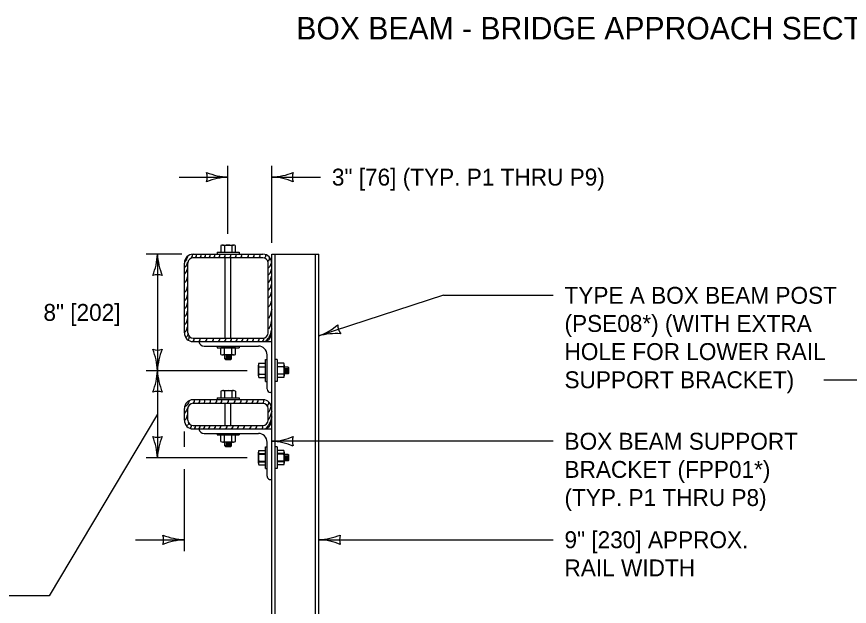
# Model space of a CAD drawing. Extents: x 49991.4 to 50021, y 49987.6 to 50011.4.
# Drawn here: x 50004.991 to 50007.949, y 49989.313 to 49991.409 of the extents above; entities that cross this region are included whole.
import ezdxf

# ---------------------------------------------------------------- set-up
doc = ezdxf.new("R2010")
doc.units = 0
for name, color, linetype in [('Level 1', 7, 'Continuous'), ('Level 2', 7, 'Continuous'), ('Level 3', 7, 'Continuous'), ('Level 4', 7, 'Continuous')]:
    doc.layers.add(name, color=color, linetype=linetype)

msp = doc.modelspace()

# ---------------------------------------------------------------- linework, layer by layer
at = {"layer": 'Level 1'}
for p, q in [((50005.7166, 49990.595), (50005.7166, 49990.5713)), ((50005.723, 49990.5966), (50005.7613, 49990.5966)), ((50005.7293, 49990.595), (50005.7293, 49990.5714)), ((50005.7551, 49990.595), (50005.7551, 49990.5714)), ((50005.7678, 49990.595), (50005.7678, 49990.5713)), ((50005.618, 49990.5649), (50005.866, 49990.5649)), ((50005.7035, 49990.5713), (50005.7811, 49990.5713)), ((50005.7035, 49990.5713), (50005.7035, 49990.5649)), ((50005.7166, 49990.5713), (50005.7678, 49990.5713)), ((50005.7811, 49990.5713), (50005.7811, 49990.5649)), ((50005.8976, 49988.7839), (50005.8976, 49990.5649)), ((50005.8976, 49990.5649), (50006.0648, 49990.5649)), ((50005.9099, 49988.7839), (50005.9099, 49990.5649)), ((50006.0527, 49988.7839), (50006.0527, 49990.5649)), ((50006.0648, 49988.7839), (50006.0648, 49990.5649)), ((50005.5872, 49990.285), (50005.5872, 49990.5333)), ((50005.5993, 49990.285), (50005.5993, 49990.5333)), ((50005.6184, 49990.5523), (50005.866, 49990.5523)), ((50005.7325, 49990.2665), (50005.7325, 49990.5523)), ((50005.7361, 49990.5523), (50005.7484, 49990.5523)), ((50005.7519, 49990.2665), (50005.7519, 49990.5523)), ((50005.8851, 49990.285), (50005.8851, 49990.5333)), ((50005.8976, 49990.285), (50005.8976, 49990.5333)), ((50005.6184, 49990.2665), (50005.866, 49990.2665)), ((50005.6184, 49990.2543), (50005.8976, 49990.2543)), ((50005.6576, 49990.2379), (50005.8503, 49990.2379)), ((50005.7038, 49990.2381), (50005.7038, 49990.2323)), ((50005.7038, 49990.2323), (50005.7814, 49990.2323)), ((50005.7681, 49990.2323), (50005.7169, 49990.2323)), ((50005.7169, 49990.2086), (50005.7169, 49990.2323)), ((50005.7296, 49990.2086), (50005.7296, 49990.2322)), ((50005.7554, 49990.2086), (50005.7554, 49990.2322)), ((50005.7681, 49990.2086), (50005.7681, 49990.2323)), ((50005.7814, 49990.2381), (50005.7814, 49990.2323)), ((50005.7617, 49990.207), (50005.7234, 49990.207)), ((50005.7308, 49990.1931), (50005.7308, 49990.207)), ((50005.7342, 49990.2037), (50005.7507, 49990.2037)), ((50005.7342, 49990.2014), (50005.7507, 49990.2014)), ((50005.7542, 49990.1931), (50005.7542, 49990.207)), ((50005.8813, 49990.0859), (50005.8813, 49990.2072)), ((50005.7542, 49990.1931), (50005.7308, 49990.1931)), ((50005.7308, 49990.1931), (50005.7331, 49990.1908)), ((50005.7331, 49990.1908), (50005.7519, 49990.1908)), ((50005.7342, 49990.199), (50005.7507, 49990.199)), ((50005.7342, 49990.1967), (50005.7507, 49990.1967)), ((50005.7542, 49990.1931), (50005.7519, 49990.1908)), ((50005.8517, 49990.1772), (50005.8754, 49990.1772)), ((50005.8754, 49990.1128), (50005.8754, 49990.1904)), ((50005.8754, 49990.1904), (50005.8817, 49990.1904)), ((50005.8754, 49990.1259), (50005.8754, 49990.1772)), ((50005.9165, 49990.1904), (50005.9102, 49990.1904)), ((50005.9165, 49990.1904), (50005.9165, 49990.1128)), ((50005.9165, 49990.1772), (50005.9165, 49990.126)), ((50005.9402, 49990.1772), (50005.9165, 49990.1772)), ((50005.8501, 49990.1324), (50005.8501, 49990.1707)), ((50005.8516, 49990.1645), (50005.8753, 49990.1645)), ((50005.9403, 49990.1645), (50005.9166, 49990.1645)), ((50005.9418, 49990.1708), (50005.9418, 49990.1325)), ((50005.9557, 49990.1633), (50005.9418, 49990.1633)), ((50005.945, 49990.1433), (50005.945, 49990.1598)), ((50005.9474, 49990.1433), (50005.9474, 49990.1598)), ((50005.9498, 49990.1433), (50005.9498, 49990.1598)), ((50005.9521, 49990.1433), (50005.9521, 49990.1598)), ((50005.9557, 49990.1633), (50005.9557, 49990.1399)), ((50005.9557, 49990.1633), (50005.958, 49990.161)), ((50005.9557, 49990.1399), (50005.958, 49990.1422)), ((50005.958, 49990.1422), (50005.958, 49990.161)), ((50005.8516, 49990.1386), (50005.8753, 49990.1386)), ((50005.8517, 49990.1259), (50005.8754, 49990.1259)), ((50005.8754, 49990.1128), (50005.8817, 49990.1128)), ((50005.9165, 49990.1128), (50005.9102, 49990.1128)), ((50005.9402, 49990.126), (50005.9165, 49990.126)), ((50005.9403, 49990.1387), (50005.9166, 49990.1387)), ((50005.9557, 49990.1399), (50005.9418, 49990.1399)), ((50005.7038, 49990.0548), (50005.7814, 49990.0548)), ((50005.7038, 49990.0548), (50005.7038, 49990.0485)), ((50005.7169, 49990.0785), (50005.7169, 49990.0548)), ((50005.7169, 49990.0548), (50005.7681, 49990.0548)), ((50005.7233, 49990.0801), (50005.7616, 49990.0801)), ((50005.7296, 49990.0785), (50005.7296, 49990.0549)), ((50005.7554, 49990.0785), (50005.7554, 49990.0549)), ((50005.7681, 49990.0785), (50005.7681, 49990.0548)), ((50005.7814, 49990.0548), (50005.7814, 49990.0485)), ((50005.8976, 49990.0733), (50005.8935, 49990.0733)), ((50005.6184, 49990.0479), (50005.866, 49990.0479)), ((50005.6184, 49990.0352), (50005.866, 49990.0352)), ((50005.7325, 49989.9565), (50005.7325, 49990.0352)), ((50005.7361, 49990.0352), (50005.7484, 49990.0352)), ((50005.7519, 49989.9565), (50005.7519, 49990.0352)), ((50005.5872, 49989.975), (50005.5872, 49990.0167)), ((50005.5993, 49989.975), (50005.5993, 49990.0167)), ((50005.8851, 49989.975), (50005.8851, 49990.0167)), ((50005.6184, 49989.9565), (50005.866, 49989.9565)), ((50005.6184, 49989.9442), (50005.8976, 49989.9442)), ((50005.6576, 49989.9279), (50005.8503, 49989.9279)), ((50005.7038, 49989.9281), (50005.7038, 49989.9222)), ((50005.7038, 49989.9222), (50005.7814, 49989.9222)), ((50005.7681, 49989.9222), (50005.7169, 49989.9222)), ((50005.7169, 49989.8985), (50005.7169, 49989.9222)), ((50005.7296, 49989.8985), (50005.7296, 49989.9221)), ((50005.7554, 49989.8985), (50005.7554, 49989.9221)), ((50005.7681, 49989.8985), (50005.7681, 49989.9222)), ((50005.7814, 49989.9281), (50005.7814, 49989.9222)), ((50005.7617, 49989.8969), (50005.7234, 49989.8969)), ((50005.7308, 49989.8831), (50005.7308, 49989.897)), ((50005.7542, 49989.8831), (50005.7308, 49989.8831)), ((50005.7308, 49989.8831), (50005.7331, 49989.8808)), ((50005.7331, 49989.8808), (50005.7519, 49989.8808)), ((50005.7342, 49989.8937), (50005.7507, 49989.8937)), ((50005.7342, 49989.8914), (50005.7507, 49989.8914)), ((50005.7342, 49989.889), (50005.7507, 49989.889)), ((50005.7342, 49989.8867), (50005.7507, 49989.8867)), ((50005.7542, 49989.8831), (50005.7519, 49989.8808)), ((50005.7542, 49989.8831), (50005.7542, 49989.897)), ((50005.8754, 49989.8029), (50005.8754, 49989.8805)), ((50005.8754, 49989.8805), (50005.8817, 49989.8805)), ((50005.8813, 49989.7759), (50005.8813, 49989.8973)), ((50005.9165, 49989.8805), (50005.9102, 49989.8805)), ((50005.9165, 49989.8805), (50005.9165, 49989.8029)), ((50005.8501, 49989.8225), (50005.8501, 49989.8608)), ((50005.8516, 49989.8546), (50005.8753, 49989.8546)), ((50005.8517, 49989.8673), (50005.8754, 49989.8673)), ((50005.8754, 49989.816), (50005.8754, 49989.8673)), ((50005.9165, 49989.8673), (50005.9165, 49989.8161)), ((50005.9402, 49989.8673), (50005.9165, 49989.8673)), ((50005.9403, 49989.8546), (50005.9166, 49989.8546)), ((50005.9418, 49989.8609), (50005.9418, 49989.8226)), ((50005.9557, 49989.8534), (50005.9418, 49989.8534)), ((50005.945, 49989.8334), (50005.945, 49989.8499)), ((50005.9474, 49989.8334), (50005.9474, 49989.8499)), ((50005.9498, 49989.8334), (50005.9498, 49989.8499)), ((50005.9521, 49989.8334), (50005.9521, 49989.8499)), ((50005.9557, 49989.8534), (50005.9557, 49989.83)), ((50005.9557, 49989.8534), (50005.958, 49989.8511)), ((50005.958, 49989.8323), (50005.958, 49989.8511)), ((50005.8516, 49989.8287), (50005.8753, 49989.8287)), ((50005.9403, 49989.8288), (50005.9166, 49989.8288)), ((50005.9557, 49989.83), (50005.9418, 49989.83)), ((50005.9557, 49989.83), (50005.958, 49989.8323)), ((50005.8517, 49989.816), (50005.8754, 49989.816)), ((50005.8754, 49989.8029), (50005.8817, 49989.8029)), ((50005.9165, 49989.8029), (50005.9102, 49989.8029)), ((50005.9402, 49989.8161), (50005.9165, 49989.8161))]:
    msp.add_line(p, q, dxfattribs=at)
for points in [[(50005.5876, 49990.5359), (50005.5931, 49990.5421), (50005.5962, 49990.5479), (50005.5988, 49990.5568)], [(50005.6088, 49990.5496), (50005.6136, 49990.5536), (50005.6156, 49990.5574), (50005.6156, 49990.5639)], [(50005.6268, 49990.5523), (50005.6305, 49990.5579), (50005.6305, 49990.5649)], [(50005.6428, 49990.5523), (50005.647, 49990.5579), (50005.6458, 49990.5649)], [(50005.6585, 49990.5523), (50005.6622, 49990.5574), (50005.6616, 49990.5639)], [(50005.6749, 49990.5523), (50005.6785, 49990.5579), (50005.6785, 49990.5639)], [(50005.6916, 49990.5523), (50005.6953, 49990.5579), (50005.6953, 49990.5639)], [(50005.7092, 49990.5523), (50005.7134, 49990.5579), (50005.7129, 49990.5639)], [(50005.7288, 49990.5523), (50005.7318, 49990.5574), (50005.7318, 49990.5639)], [(50005.7478, 49990.5523), (50005.7515, 49990.5579), (50005.7515, 49990.5639)], [(50005.7672, 49990.5523), (50005.771, 49990.5579), (50005.771, 49990.5639)], [(50005.7874, 49990.5523), (50005.7911, 49990.5579), (50005.7904, 49990.5639)], [(50005.8112, 49990.5523), (50005.8143, 49990.5579), (50005.8143, 49990.5649)], [(50005.8312, 49990.5523), (50005.8353, 49990.5579), (50005.8348, 49990.5639)], [(50005.8516, 49990.5523), (50005.856, 49990.5579), (50005.855, 49990.5639)], [(50005.8718, 49990.5512), (50005.8762, 49990.5568), (50005.8762, 49990.5632)], [(50005.5867, 49990.5171), (50005.5931, 49990.5227), (50005.5966, 49990.5299), (50005.5993, 49990.5373)], [(50005.8857, 49990.5401), (50005.8888, 49990.5459), (50005.8888, 49990.5523)], [(50005.8861, 49990.5159), (50005.8919, 49990.5221), (50005.8945, 49990.5279), (50005.8972, 49990.5373)], [(50005.5876, 49990.4941), (50005.5931, 49990.5008), (50005.5962, 49990.5067), (50005.5988, 49990.5159)], [(50005.8861, 49990.491), (50005.8915, 49990.4968), (50005.894, 49990.503), (50005.8968, 49990.5114)], [(50005.5872, 49990.4628), (50005.5931, 49990.4693), (50005.5958, 49990.4751), (50005.5982, 49990.4842)], [(50005.8861, 49990.4645), (50005.8915, 49990.4709), (50005.894, 49990.4777), (50005.8968, 49990.4862)], [(50005.5872, 49990.4287), (50005.5931, 49990.4348), (50005.5958, 49990.4407), (50005.5982, 49990.4498)], [(50005.8861, 49990.4371), (50005.8915, 49990.4434), (50005.894, 49990.4491), (50005.8968, 49990.4583)], [(50005.5876, 49990.399), (50005.5931, 49990.4052), (50005.5962, 49990.4112), (50005.5982, 49990.4202)], [(50005.8861, 49990.4095), (50005.8915, 49990.4153), (50005.894, 49990.4219), (50005.8968, 49990.4301)], [(50005.5876, 49990.3705), (50005.5931, 49990.3763), (50005.5962, 49990.3826), (50005.5982, 49990.3915)], [(50005.8861, 49990.3773), (50005.8915, 49990.3831), (50005.894, 49990.3889), (50005.8968, 49990.3983)], [(50005.5876, 49990.3415), (50005.5931, 49990.3479), (50005.5962, 49990.3537), (50005.5982, 49990.3626)], [(50005.8972, 49990.3683), (50005.8945, 49990.3571), (50005.8915, 49990.3466), (50005.8857, 49990.3361)], [(50005.5876, 49990.3135), (50005.5931, 49990.3197), (50005.5962, 49990.3255), (50005.5982, 49990.3346)], [(50005.8968, 49990.3308), (50005.8945, 49990.3197), (50005.8915, 49990.3091), (50005.8857, 49990.2986)], [(50005.5876, 49990.2866), (50005.5931, 49990.2927), (50005.5962, 49990.2986), (50005.5982, 49990.3071)], [(50005.8972, 49990.2996), (50005.8945, 49990.289), (50005.8915, 49990.278), (50005.8857, 49990.2675), (50005.8766, 49990.2569)], [(50005.6003, 49990.2839), (50005.5982, 49990.276), (50005.5962, 49990.2712), (50005.5915, 49990.2696)], [(50005.6014, 49990.2607), (50005.6046, 49990.2665), (50005.6046, 49990.2723)], [(50005.6184, 49990.2543), (50005.622, 49990.2607), (50005.6214, 49990.2665)], [(50005.6395, 49990.2543), (50005.6432, 49990.2601), (50005.6432, 49990.2659)], [(50005.6622, 49990.2543), (50005.6664, 49990.2601), (50005.6664, 49990.2659)], [(50005.6875, 49990.2543), (50005.6907, 49990.2607), (50005.6907, 49990.2665)], [(50005.7087, 49990.2543), (50005.7129, 49990.2607), (50005.7124, 49990.2665)], [(50005.7297, 49990.2543), (50005.7341, 49990.2607), (50005.7331, 49990.2665)], [(50005.7504, 49990.2549), (50005.754, 49990.2607), (50005.754, 49990.2665)], [(50005.7704, 49990.2549), (50005.7747, 49990.2607), (50005.7737, 49990.2669)], [(50005.79, 49990.2543), (50005.7942, 49990.2607), (50005.7937, 49990.2665)], [(50005.8084, 49990.2543), (50005.8122, 49990.2607), (50005.8122, 49990.2665)], [(50005.8292, 49990.2543), (50005.8328, 49990.2607), (50005.8328, 49990.2665)], [(50005.8486, 49990.2543), (50005.8528, 49990.2601), (50005.8528, 49990.2665)], [(50005.865, 49990.2543), (50005.8688, 49990.2601), (50005.8688, 49990.2665)], [(50005.6046, 49990.0436), (50005.6014, 49990.0361), (50005.5972, 49990.0294), (50005.5935, 49990.0256), (50005.5876, 49990.0208)], [(50005.62, 49990.0352), (50005.6235, 49990.041), (50005.6235, 49990.0462)], [(50005.6384, 49990.0352), (50005.6422, 49990.041), (50005.6422, 49990.0462)], [(50005.6564, 49990.0345), (50005.66, 49990.041), (50005.66, 49990.0462)], [(50005.6769, 49990.0352), (50005.6801, 49990.041), (50005.6801, 49990.0462)], [(50005.698, 49990.0352), (50005.7018, 49990.041), (50005.7018, 49990.0462)], [(50005.7171, 49990.0352), (50005.7202, 49990.041), (50005.7202, 49990.0462)], [(50005.7403, 49990.0352), (50005.7435, 49990.041), (50005.7435, 49990.0462)], [(50005.7641, 49990.0361), (50005.7672, 49990.0419), (50005.7672, 49990.0467)], [(50005.7852, 49990.0352), (50005.7893, 49990.041), (50005.7891, 49990.0462)], [(50005.8056, 49990.0352), (50005.8095, 49990.041), (50005.8095, 49990.0462)], [(50005.8276, 49990.0361), (50005.8312, 49990.0419), (50005.8312, 49990.0467)], [(50005.8453, 49990.0361), (50005.8486, 49990.0419), (50005.8486, 49990.0467)], [(50005.8656, 49990.0345), (50005.8691, 49990.041), (50005.8691, 49990.0467)], [(50005.8824, 49990.0266), (50005.8868, 49990.0325), (50005.8868, 49990.0389)], [(50005.895, 49990.0263), (50005.8919, 49990.0157), (50005.8877, 49990.0059), (50005.8851, 49990.0019)], [(50005.6003, 49990.0219), (50005.5972, 49990.0151), (50005.5935, 49990.0076), (50005.5872, 49990.0001)], [(50005.8972, 49990.0072), (50005.8945, 49989.9956), (50005.8909, 49989.9855), (50005.8851, 49989.977)], [(50005.5876, 49989.9735), (50005.5931, 49989.9797), (50005.5962, 49989.9855), (50005.5982, 49989.9939)], [(50005.602, 49989.9655), (50005.6014, 49989.9616), (50005.5988, 49989.9571), (50005.5952, 49989.9555)], [(50005.8976, 49989.9871), (50005.8945, 49989.975), (50005.8909, 49989.9655), (50005.8857, 49989.9575)], [(50005.6088, 49989.9463), (50005.6125, 49989.9521), (50005.6125, 49989.9575)], [(50005.6225, 49989.9442), (50005.6268, 49989.95), (50005.6262, 49989.9559)], [(50005.64, 49989.9449), (50005.6436, 49989.9507), (50005.6436, 49989.9559)], [(50005.6558, 49989.9449), (50005.66, 49989.9507), (50005.66, 49989.9559)], [(50005.6744, 49989.9449), (50005.678, 49989.9507), (50005.678, 49989.9559)], [(50005.6932, 49989.9442), (50005.6971, 49989.95), (50005.6964, 49989.9555)], [(50005.7134, 49989.9449), (50005.7171, 49989.9507), (50005.7171, 49989.9559)], [(50005.7351, 49989.9449), (50005.7387, 49989.9507), (50005.7383, 49989.9559)], [(50005.7556, 49989.9449), (50005.76, 49989.9507), (50005.7594, 49989.9559)], [(50005.7762, 49989.9449), (50005.7795, 49989.9507), (50005.7795, 49989.9559)], [(50005.7968, 49989.9449), (50005.8009, 49989.9507), (50005.8006, 49989.9559)], [(50005.82, 49989.9449), (50005.8238, 49989.9507), (50005.8238, 49989.9559)], [(50005.8407, 49989.9449), (50005.8449, 49989.9507), (50005.8444, 49989.9559)], [(50005.8628, 49989.9442), (50005.866, 49989.95), (50005.866, 49989.9555)], [(50005.8857, 49989.9575), (50005.8772, 49989.9463)]]:
    msp.add_lwpolyline(points, dxfattribs=at)
for centre, radius, start, end in [((50005.618, 49990.5332), 0.031, 90, 180), ((50005.8661, 49990.5332), 0.031, 0, 90), ((50005.618, 49990.5332), 0.0186, 90, 180), ((50005.8661, 49990.5332), 0.0186, 0, 90), ((50005.618, 49990.2851), 0.031, 180, 270), ((50005.618, 49990.2851), 0.0186, 180, 270), ((50005.8661, 49990.2851), 0.031, 270, 0), ((50005.8661, 49990.2851), 0.0186, 270, 0), ((50005.6572, 49990.2566), 0.0186, 187.6623, 270), ((50005.85, 49990.2069), 0.031, 0, 90), ((50005.8934, 49990.0855), 0.0124, 180, 270), ((50005.618, 49990.0162), 0.031, 90, 180), ((50005.618, 49990.0162), 0.0186, 90, 180), ((50005.8661, 49990.0162), 0.031, 0, 90), ((50005.8661, 49990.0162), 0.0186, 0, 90), ((50005.618, 49989.9748), 0.031, 180, 270), ((50005.618, 49989.9748), 0.0186, 180, 270), ((50005.8661, 49989.9748), 0.0186, 270, 0), ((50005.8661, 49989.9748), 0.031, 270, 0), ((50005.6572, 49989.9463), 0.0186, 187.6623, 270), ((50005.85, 49989.8967), 0.031, 0, 90), ((50005.8937, 49989.7759), 0.0124, 180, 287.0542)]:
    msp.add_arc(centre, radius, start, end, dxfattribs=at)
for centre, major_axis, start_param, end_param in [((50005.723, 49990.5846), (0.0128, 0), 1.056847, 2.094396), ((50005.7422, 49990.5486), (0.0512, 0), 1.315951, 1.825641), ((50005.7614, 49990.5846), (0.0128, 0), 1.047198, 2.084746), ((50005.7233, 49990.219), (-0.0128, 0), 1.047198, 2.084746), ((50005.7425, 49990.255), (-0.0512, 0), 1.315951, 1.825641), ((50005.7617, 49990.219), (-0.0128, 0), 1.056847, 2.094396), ((50005.8621, 49990.1708), (0, 0.0128), 1.047198, 2.084746), ((50005.9298, 49990.1708), (0, -0.0128), 1.056847, 2.094396), ((50005.898, 49990.1516), (0, 0.0512), 1.315951, 1.825641), ((50005.8939, 49990.1516), (0, -0.0512), 1.315951, 1.825641), ((50005.8621, 49990.1323), (0, 0.0128), 1.056847, 2.094396), ((50005.9298, 49990.1324), (0, -0.0128), 1.047198, 2.084746), ((50005.7233, 49990.0681), (0.0128, 0), 1.056847, 2.094396), ((50005.7425, 49990.0321), (0.0512, 0), 1.315951, 1.825641), ((50005.7617, 49990.0681), (0.0128, 0), 1.047198, 2.084746), ((50005.7233, 49989.9089), (-0.0128, 0), 1.047198, 2.084746), ((50005.7425, 49989.9449), (-0.0512, 0), 1.315951, 1.825641), ((50005.7617, 49989.9089), (-0.0128, 0), 1.056847, 2.094396), ((50005.8621, 49989.8609), (0, 0.0128), 1.047198, 2.084746), ((50005.898, 49989.8417), (0, 0.0512), 1.315951, 1.825641), ((50005.9298, 49989.8609), (0, -0.0128), 1.056847, 2.094396), ((50005.8939, 49989.8417), (0, -0.0512), 1.315951, 1.825641), ((50005.8621, 49989.8224), (0, 0.0128), 1.056847, 2.094396), ((50005.9298, 49989.8225), (0, -0.0128), 1.047198, 2.084746)]:
    msp.add_ellipse(centre, major_axis=major_axis, ratio=0.93686, start_param=start_param, end_param=end_param, dxfattribs=at)
at = {"layer": 'Level 3'}
for p, q in [((50005.7419, 49990.6366), (50005.7419, 49990.8785)), ((50005.8976, 49990.6049), (50005.8976, 49990.8785)), ((50005.5685, 49990.8385), (50005.7419, 49990.8385)), ((50005.8976, 49990.8385), (50006.071, 49990.8385)), ((50005.5784, 49990.5649), (50005.4515, 49990.5649)), ((50005.4915, 49990.5649), (50005.4915, 49990.1507)), ((50006.5069, 49990.4185), (50006.0648, 49990.274)), ((50006.5069, 49990.4185), (50006.8971, 49990.4185)), ((50005.8101, 49990.1507), (50005.4515, 49990.1507)), ((50005.4915, 49990.1507), (50005.4915, 49989.8407)), ((50007.8581, 49990.1185), (50008.4571, 49990.1185)), ((50005.4915, 49989.9957), (50005.1074, 49989.3501)), ((50005.5869, 49989.9348), (50005.5869, 49989.8807)), ((50006.8971, 49989.8999), (50005.8976, 49989.8999)), ((50005.8101, 49989.8407), (50005.4515, 49989.8407)), ((50005.5869, 49989.8007), (50005.5869, 49989.5099)), ((50005.4135, 49989.5499), (50005.5869, 49989.5499)), ((50006.0648, 49989.5499), (50006.8971, 49989.5499)), ((50005.1074, 49989.3501), (50004.7612, 49989.3501))]:
    msp.add_line(p, q, dxfattribs=at)
for centre, radius, start, end in [((50005.7511, 49991.0607), 0.2223, 247.456, 267.6395), ((50005.6137, 49990.8385), 0.0548, 342.1388, 17.8612), ((50005.8861, 49991.0712), 0.233, 272.8273, 292.0772), ((50006.0258, 49990.8385), 0.0548, 162.1388, 197.8612), ((50005.7534, 49990.6058), 0.233, 92.8273, 112.0772), ((50005.8884, 49990.6164), 0.2223, 67.456, 87.6395), ((50005.2694, 49990.5741), 0.2223, 337.456, 357.6395), ((50005.7242, 49990.5764), 0.233, 182.8273, 202.0772), ((50005.4915, 49990.4367), 0.0548, 72.1388, 107.8612), ((50005.9816, 49990.4917), 0.233, 290.9234, 310.1732), ((50006.1867, 49990.3139), 0.0548, 180.2349, 215.9573), ((50006.1251, 49990.0601), 0.2223, 85.5521, 105.7356), ((50005.4915, 49990.2789), 0.0548, 252.1388, 287.8612), ((50005.2588, 49990.1392), 0.233, 2.8273, 22.0772), ((50005.7136, 49990.1415), 0.2223, 157.456, 177.6395), ((50005.2694, 49990.1599), 0.2223, 337.456, 357.6395), ((50005.7242, 49990.1622), 0.233, 182.8273, 202.0772), ((50005.4915, 49990.0225), 0.0548, 72.1388, 107.8612), ((50005.4915, 49989.9689), 0.0548, 252.1388, 287.8612), ((50005.2588, 49989.8292), 0.233, 2.8273, 22.0772), ((50005.7136, 49989.8315), 0.2223, 157.456, 177.6395), ((50005.8861, 49990.1326), 0.233, 272.8273, 292.0772), ((50006.0258, 49989.8999), 0.0548, 162.1388, 197.8612), ((50005.8884, 49989.6777), 0.2223, 67.456, 87.6395), ((50005.5961, 49989.7721), 0.2223, 247.456, 267.6395), ((50005.4587, 49989.5499), 0.0548, 342.1388, 17.8612), ((50006.0533, 49989.7827), 0.233, 272.8273, 292.0772), ((50006.193, 49989.5499), 0.0548, 162.1388, 197.8612), ((50005.5984, 49989.3172), 0.233, 92.8273, 112.0772), ((50006.0556, 49989.3278), 0.2223, 67.456, 87.6395)]:
    msp.add_arc(centre, radius, start, end, dxfattribs=at)
at = {"layer": 'Level 4'}
for p, q in [((50005.851, 49989.856), (50005.8754, 49989.856)), ((50005.9409, 49989.8561), (50005.9165, 49989.8561)), ((50005.851, 49989.8273), (50005.8754, 49989.8273)), ((50005.9409, 49989.8274), (50005.9165, 49989.8274))]:
    msp.add_line(p, q, dxfattribs=at)

# ---------------------------------------------------------------- texts
at = {"layer": 'Level 2'}
for s, height, p in [('BOX BEAM - BRIDGE APPROACH SECTION TYPE 2', 0.08, (50005.9846, 49991.3275)), ('3" [76] (TYP. P1 THRU P9)', 0.06, (50006.111, 49990.8085)), ('TYPE A BOX BEAM POST', 0.06, (50006.9371, 49990.3885)), ('8" [202]', 0.06, (50005.0865, 49990.3278)), ('(PSE08*) (WITH EXTRA', 0.06, (50006.9371, 49990.2885)), ('HOLE FOR LOWER RAIL', 0.06, (50006.9371, 49990.1885)), ('SUPPORT BRACKET)', 0.06, (50006.9371, 49990.0885)), ('BOX BEAM SUPPORT', 0.06, (50006.9371, 49989.8699)), ('BRACKET (FPP01*)', 0.06, (50006.9371, 49989.7699)), ('(TYP. P1 THRU P8)', 0.06, (50006.9371, 49989.6699)), ('9" [230] APPROX.', 0.06, (50006.9371, 49989.52)), ('RAIL WIDTH', 0.06, (50006.9371, 49989.42))]:
    msp.add_text(s, height=height, dxfattribs=at).set_placement(p)

doc.saveas('drawing.dxf')
